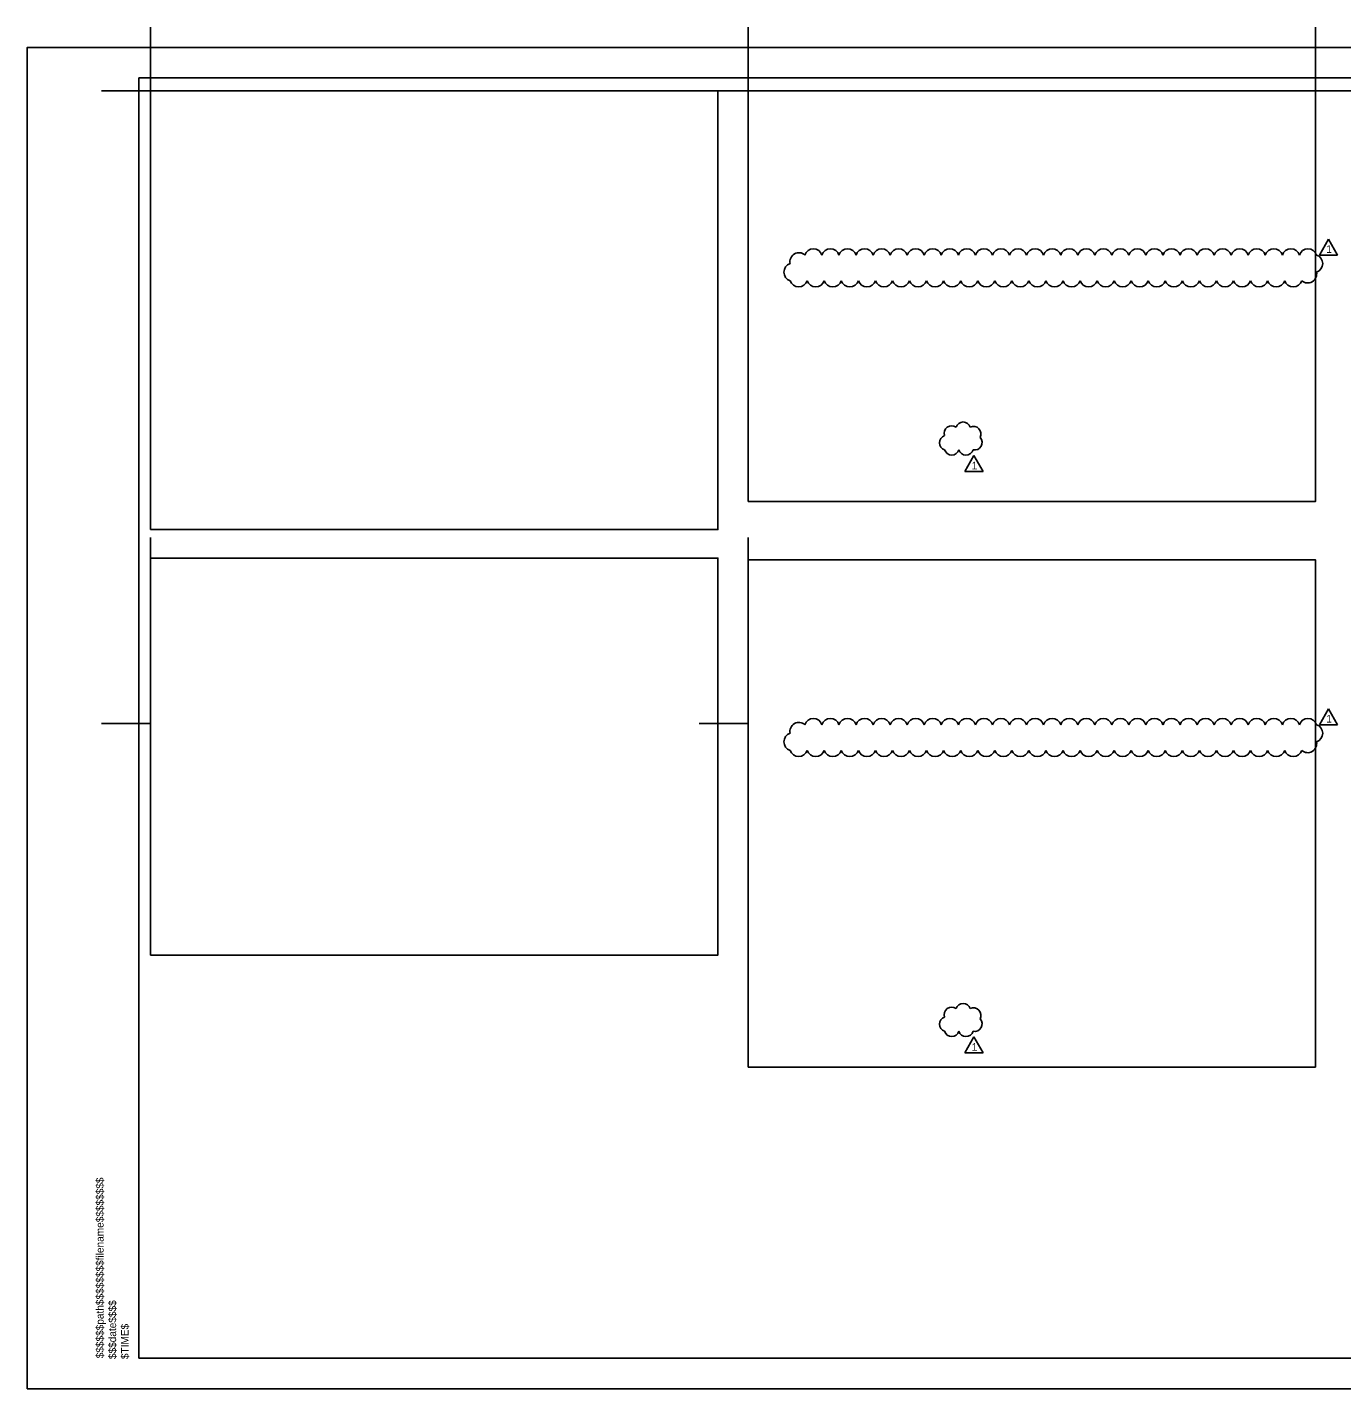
# Model space of a CAD drawing. Extents: x -121.2 to -24.9, y 6.4 to 65.9.
# Drawn here: x -121.2 to -63.6, y 6.4 to 65.9 of the extents above; entities that cross this region are included whole.
import ezdxf

# ---------------------------------------------------------------- set-up
doc = ezdxf.new("R2010")
doc.units = 0
for name, color, linetype in [('BR_AUTO DIMENSION', 7, 'Continuous'), ('BR_BORDER LINES', 7, 'Continuous'), ('BR_TEXT', 7, 'Continuous'), ('Level 31', 7, 'Continuous'), ('RD_SHT_ID', 7, 'Continuous')]:
    doc.layers.add(name, color=color, linetype=linetype)

msp = doc.modelspace()

# ---------------------------------------------------------------- linework, layer by layer
at = {"layer": 'BR_AUTO DIMENSION'}
for points in [[(-115.765, 43.933), (-90.936, 43.933), (-90.936, 63.127), (-115.765, 63.127)], [(-115.765, 25.32), (-90.936, 25.32), (-90.936, 42.683), (-115.765, 42.683)]]:
    msp.add_lwpolyline(points, close=True, dxfattribs=at)
at = {"layer": 'BR_BORDER LINES'}
for p, q in [((-26.496, 63.683), (-116.272, 63.683)), ((-116.272, 7.683), (-116.272, 63.683)), ((-116.272, 7.683), (-26.496, 7.683))]:
    msp.add_line(p, q, dxfattribs=at)
at = {"layer": 'BR_TEXT'}
for p, q in [((-64.611, 55.939), (-64.211, 56.631)), ((-63.811, 55.939), (-64.211, 56.631)), ((-64.611, 55.939), (-63.811, 55.939)), ((-80.128, 46.473), (-79.728, 47.166)), ((-79.328, 46.473), (-79.728, 47.166)), ((-80.128, 46.473), (-79.328, 46.473)), ((-64.611, 35.395), (-64.211, 36.088)), ((-63.811, 35.395), (-64.211, 36.088)), ((-64.611, 35.395), (-63.811, 35.395)), ((-80.128, 21.043), (-79.728, 21.736)), ((-79.328, 21.043), (-79.728, 21.736)), ((-80.128, 21.043), (-79.328, 21.043))]:
    msp.add_line(p, q, dxfattribs=at)
for centre, radius, start, end in [((-87.389, 55.649), 0.391, 47.81918, 192.81918), ((-86.754, 55.821), 0.391, 17.5, 162.5), ((-86.007, 55.821), 0.391, 17.5, 162.5), ((-85.261, 55.821), 0.391, 17.5, 162.5), ((-84.515, 55.821), 0.391, 17.5, 162.5), ((-83.768, 55.821), 0.391, 17.5, 162.5), ((-83.022, 55.821), 0.391, 17.5, 162.5), ((-82.276, 55.821), 0.391, 17.5, 162.5), ((-81.529, 55.821), 0.391, 17.5, 162.5), ((-80.783, 55.821), 0.391, 17.5, 162.5), ((-80.037, 55.821), 0.391, 17.5, 162.5), ((-79.291, 55.821), 0.391, 17.5, 162.5), ((-78.544, 55.821), 0.391, 17.5, 162.5), ((-77.798, 55.821), 0.391, 17.5, 162.5), ((-77.052, 55.821), 0.391, 17.5, 162.5), ((-76.305, 55.821), 0.391, 17.5, 162.5), ((-75.559, 55.821), 0.391, 17.5, 162.5), ((-74.813, 55.821), 0.391, 17.5, 162.5), ((-74.066, 55.821), 0.391, 17.5, 162.5), ((-73.32, 55.821), 0.391, 17.5, 162.5), ((-72.574, 55.821), 0.391, 17.5, 162.5), ((-71.827, 55.821), 0.391, 17.5, 162.5), ((-71.081, 55.821), 0.391, 17.5, 162.5), ((-70.335, 55.821), 0.391, 17.5, 162.5), ((-69.589, 55.821), 0.391, 17.5, 162.5), ((-68.842, 55.821), 0.391, 17.5, 162.5), ((-68.096, 55.821), 0.391, 17.5, 162.5), ((-67.35, 55.821), 0.391, 17.5, 162.5), ((-66.603, 55.821), 0.391, 17.5, 162.5), ((-65.857, 55.821), 0.391, 17.5, 162.5), ((-65.111, 55.821), 0.391, 17.5, 162.5), ((-87.653, 55.189), 0.391, 107.5, 252.5), ((-64.855, 55.566), 0.391, 287.5, 72.5), ((-87.398, 54.934), 0.391, 197.5, 342.5), ((-86.651, 54.934), 0.391, 197.5, 342.5), ((-85.905, 54.934), 0.391, 197.5, 342.5), ((-85.159, 54.934), 0.391, 197.5, 342.5), ((-84.412, 54.934), 0.391, 197.5, 342.5), ((-83.666, 54.934), 0.391, 197.5, 342.5), ((-82.92, 54.934), 0.391, 197.5, 342.5), ((-82.174, 54.934), 0.391, 197.5, 342.5), ((-81.427, 54.934), 0.391, 197.5, 342.5), ((-80.681, 54.934), 0.391, 197.5, 342.5), ((-79.935, 54.934), 0.391, 197.5, 342.5), ((-79.188, 54.934), 0.391, 197.5, 342.5), ((-78.442, 54.934), 0.391, 197.5, 342.5), ((-77.696, 54.934), 0.391, 197.5, 342.5), ((-76.949, 54.934), 0.391, 197.5, 342.5), ((-76.203, 54.934), 0.391, 197.5, 342.5), ((-75.457, 54.934), 0.391, 197.5, 342.5), ((-74.71, 54.934), 0.391, 197.5, 342.5), ((-73.964, 54.934), 0.391, 197.5, 342.5), ((-73.218, 54.934), 0.391, 197.5, 342.5), ((-72.472, 54.934), 0.391, 197.5, 342.5), ((-71.725, 54.934), 0.391, 197.5, 342.5), ((-70.979, 54.934), 0.391, 197.5, 342.5), ((-70.233, 54.934), 0.391, 197.5, 342.5), ((-69.486, 54.934), 0.391, 197.5, 342.5), ((-68.74, 54.934), 0.391, 197.5, 342.5), ((-67.994, 54.934), 0.391, 197.5, 342.5), ((-67.247, 54.934), 0.391, 197.5, 342.5), ((-66.501, 54.934), 0.391, 197.5, 342.5), ((-65.755, 54.934), 0.391, 197.5, 342.5), ((-65.119, 55.106), 0.391, 227.81918, 12.81918), ((-80.702, 48.144), 0.326, 53.97923, 198.97923), ((-80.199, 48.31), 0.326, 17.5, 162.5), ((-79.745, 48.115), 0.326, 331.03988, 116.03988), ((-80.913, 47.727), 0.326, 107.5, 252.5), ((-79.698, 47.735), 0.326, 257.96211, 42.96211), ((-80.7, 47.514), 0.326, 197.5, 342.5), ((-80.077, 47.514), 0.326, 197.5, 342.5), ((-87.389, 35.106), 0.391, 47.81918, 192.81918), ((-86.754, 35.278), 0.391, 17.5, 162.5), ((-86.007, 35.278), 0.391, 17.5, 162.5), ((-85.261, 35.278), 0.391, 17.5, 162.5), ((-84.515, 35.278), 0.391, 17.5, 162.5), ((-83.768, 35.278), 0.391, 17.5, 162.5), ((-83.022, 35.278), 0.391, 17.5, 162.5), ((-82.276, 35.278), 0.391, 17.5, 162.5), ((-81.529, 35.278), 0.391, 17.5, 162.5), ((-80.783, 35.278), 0.391, 17.5, 162.5), ((-80.037, 35.278), 0.391, 17.5, 162.5), ((-79.291, 35.278), 0.391, 17.5, 162.5), ((-78.544, 35.278), 0.391, 17.5, 162.5), ((-77.798, 35.278), 0.391, 17.5, 162.5), ((-77.052, 35.278), 0.391, 17.5, 162.5), ((-76.305, 35.278), 0.391, 17.5, 162.5), ((-75.559, 35.278), 0.391, 17.5, 162.5), ((-74.813, 35.278), 0.391, 17.5, 162.5), ((-74.066, 35.278), 0.391, 17.5, 162.5), ((-73.32, 35.278), 0.391, 17.5, 162.5), ((-72.574, 35.278), 0.391, 17.5, 162.5), ((-71.827, 35.278), 0.391, 17.5, 162.5), ((-71.081, 35.278), 0.391, 17.5, 162.5), ((-70.335, 35.278), 0.391, 17.5, 162.5), ((-69.589, 35.278), 0.391, 17.5, 162.5), ((-68.842, 35.278), 0.391, 17.5, 162.5), ((-68.096, 35.278), 0.391, 17.5, 162.5), ((-67.35, 35.278), 0.391, 17.5, 162.5), ((-66.603, 35.278), 0.391, 17.5, 162.5), ((-65.857, 35.278), 0.391, 17.5, 162.5), ((-65.111, 35.278), 0.391, 17.5, 162.5), ((-64.855, 35.022), 0.391, 287.5, 72.5), ((-87.653, 34.646), 0.391, 107.5, 252.5), ((-65.119, 34.562), 0.391, 227.81918, 12.81918), ((-87.398, 34.39), 0.391, 197.5, 342.5), ((-86.651, 34.39), 0.391, 197.5, 342.5), ((-85.905, 34.39), 0.391, 197.5, 342.5), ((-85.159, 34.39), 0.391, 197.5, 342.5), ((-84.412, 34.39), 0.391, 197.5, 342.5), ((-83.666, 34.39), 0.391, 197.5, 342.5), ((-82.92, 34.39), 0.391, 197.5, 342.5), ((-82.174, 34.39), 0.391, 197.5, 342.5), ((-81.427, 34.39), 0.391, 197.5, 342.5), ((-80.681, 34.39), 0.391, 197.5, 342.5), ((-79.935, 34.39), 0.391, 197.5, 342.5), ((-79.188, 34.39), 0.391, 197.5, 342.5), ((-78.442, 34.39), 0.391, 197.5, 342.5), ((-77.696, 34.39), 0.391, 197.5, 342.5), ((-76.949, 34.39), 0.391, 197.5, 342.5), ((-76.203, 34.39), 0.391, 197.5, 342.5), ((-75.457, 34.39), 0.391, 197.5, 342.5), ((-74.71, 34.39), 0.391, 197.5, 342.5), ((-73.964, 34.39), 0.391, 197.5, 342.5), ((-73.218, 34.39), 0.391, 197.5, 342.5), ((-72.472, 34.39), 0.391, 197.5, 342.5), ((-71.725, 34.39), 0.391, 197.5, 342.5), ((-70.979, 34.39), 0.391, 197.5, 342.5), ((-70.233, 34.39), 0.391, 197.5, 342.5), ((-69.486, 34.39), 0.391, 197.5, 342.5), ((-68.74, 34.39), 0.391, 197.5, 342.5), ((-67.994, 34.39), 0.391, 197.5, 342.5), ((-67.247, 34.39), 0.391, 197.5, 342.5), ((-66.501, 34.39), 0.391, 197.5, 342.5), ((-65.755, 34.39), 0.391, 197.5, 342.5), ((-80.702, 22.714), 0.326, 53.97923, 198.97923), ((-80.199, 22.88), 0.326, 17.5, 162.5), ((-79.745, 22.685), 0.326, 331.03988, 116.03988), ((-80.913, 22.297), 0.326, 107.5, 252.5), ((-79.698, 22.305), 0.326, 257.96211, 42.96211), ((-80.7, 22.084), 0.326, 197.5, 342.5), ((-80.077, 22.084), 0.326, 197.5, 342.5)]:
    msp.add_arc(centre, radius, start, end, dxfattribs=at)
at = {"layer": 'Level 31'}
for p, q in [((-115.765, 63.127), (-115.765, 65.902)), ((-89.607, 63.127), (-89.607, 65.902)), ((-64.775, 63.127), (-64.775, 65.902)), ((-115.765, 63.127), (-117.912, 63.127)), ((-89.607, 63.127), (-91.754, 63.127)), ((-63.448, 63.127), (-65.595, 63.127)), ((-64.775, 63.127), (-60.127, 63.127)), ((-115.765, 35.444), (-115.765, 43.582)), ((-89.607, 35.444), (-89.607, 43.582)), ((-115.765, 35.444), (-117.912, 35.444)), ((-89.607, 35.444), (-91.754, 35.444))]:
    msp.add_line(p, q, dxfattribs=at)
for points in [[(-121.161, 6.35), (-25.161, 6.35), (-25.161, 65.017), (-121.161, 65.017)], [(-89.607, 45.163), (-64.775, 45.163), (-64.775, 63.127), (-89.607, 63.127)], [(-89.607, 20.423), (-64.78, 20.423), (-64.78, 42.609), (-89.607, 42.609)]]:
    msp.add_lwpolyline(points, close=True, dxfattribs=at)

# ---------------------------------------------------------------- texts
at = {"layer": 'BR_TEXT'}
for p in [(-64.308, 56.029), (-79.826, 46.564), (-64.308, 35.486), (-79.826, 21.134)]:
    msp.add_text('1', height=0.333, rotation=360, dxfattribs=at).set_placement(p)
at = {"layer": 'RD_SHT_ID'}
for s, height, p in [('$$$$$$path$$$$$$$$filename$$$$$$$$', 0.32925, (-117.818, 7.683)), ('$$$date$$$$', 0.32925, (-117.269, 7.649)), ('$TIME$', 0.3292, (-116.723, 7.649))]:
    msp.add_text(s, height=height, rotation=90, dxfattribs=at).set_placement(p)

doc.saveas('drawing.dxf')
